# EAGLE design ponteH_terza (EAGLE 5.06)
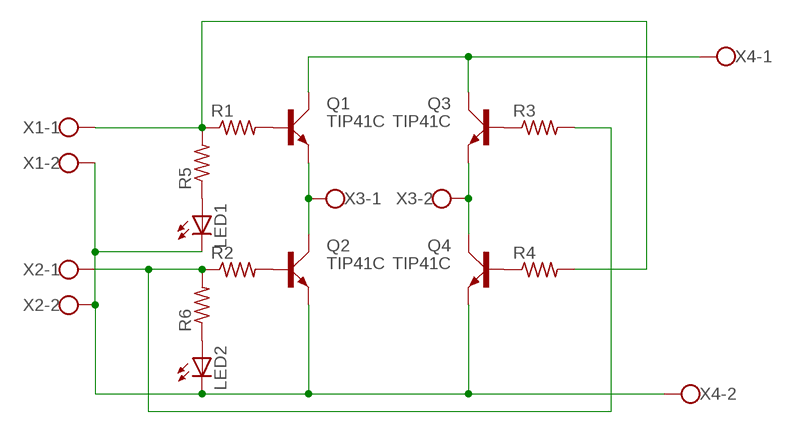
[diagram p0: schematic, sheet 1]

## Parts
LED1  LED3MM  [LED3MM]
LED2  LED3MM  [LED3MM]
Q1  TIP41C  [TO220AV]
Q2  TIP41C  [TO220AV]
Q3  TIP41C  [TO220AV]
Q4  TIP41C  [TO220AV]
R1  R-US_0207/10  [0207/10]
R2  R-US_0207/10  [0207/10]
R3  R-US_0207/10  [0207/10]
R4  R-US_0207/10  [0207/10]
R5  R-US_0207/10  [0207/10]
R6  R-US_0207/10  [0207/10]
X1  W237-02P  [W237-132]
X2  W237-02P  [W237-132]
X3  W237-02P  [W237-132]
X4  W237-02P  [W237-132]

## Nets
N$1: Q1.B R1.2
N$2: Q2.B R2.2
N$3: Q3.B R3.1
N$4: Q4.B R4.1
N$5: R1.1 R4.2 R5.2 X1.1
N$6: R2.1 R3.2 R6.2 X2.1
N$7: LED1.A R5.1
N$8: LED2.A R6.1
N$9: Q1.C Q3.C X4.1
N$10: Q3.E Q4.C X3.2
N$11: Q1.E Q2.C X3.1
N$12: LED1.K(C) LED2.K(C) Q2.E Q4.E X1.2 X2.2 X4.2

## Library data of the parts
LED1 LED2 = led:LED: LED
Q1-Q4 = transistor-power:TIP41C: NPN TRANSISTOR
R1-R6 = resistor:R-US_: RESISTOR, American symbol
X1-X4 = con-wago-508:W237-02P: WAGO SREW CLAMP

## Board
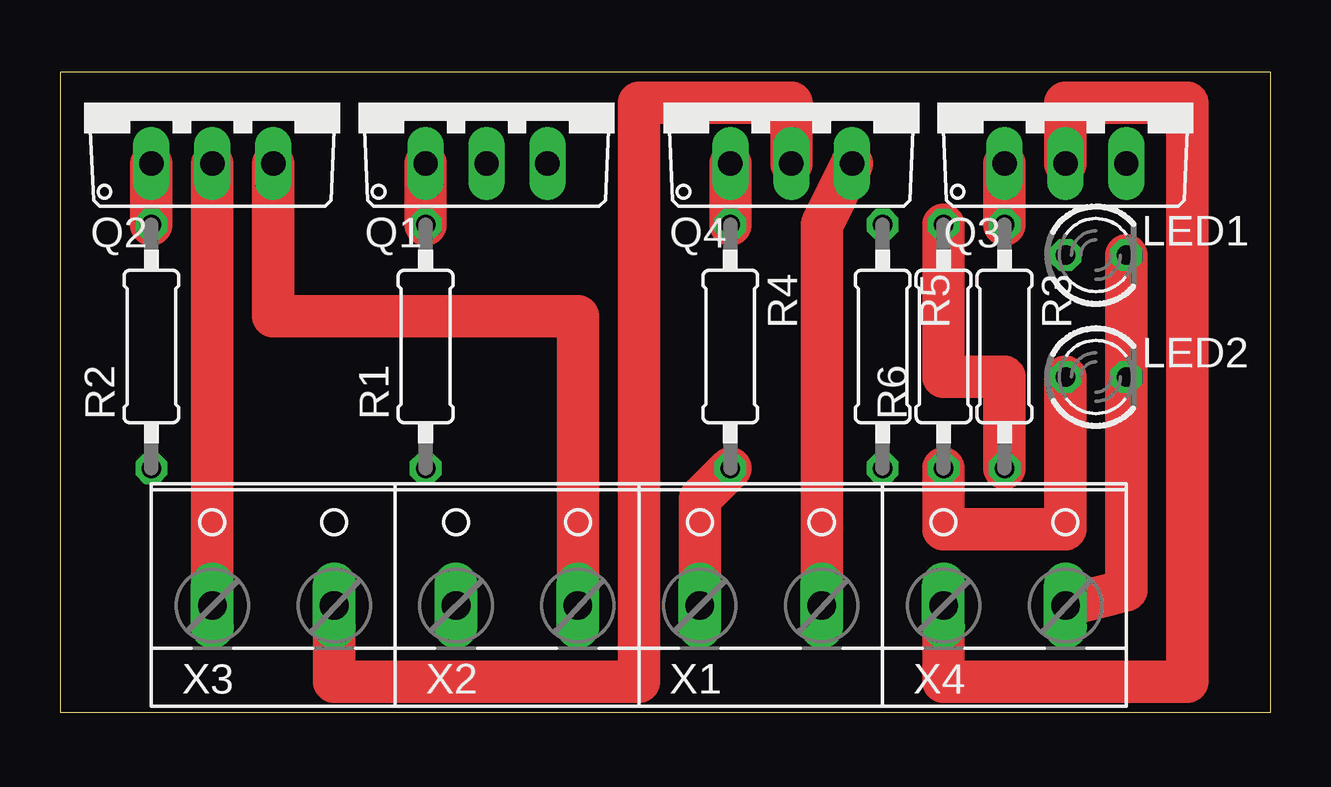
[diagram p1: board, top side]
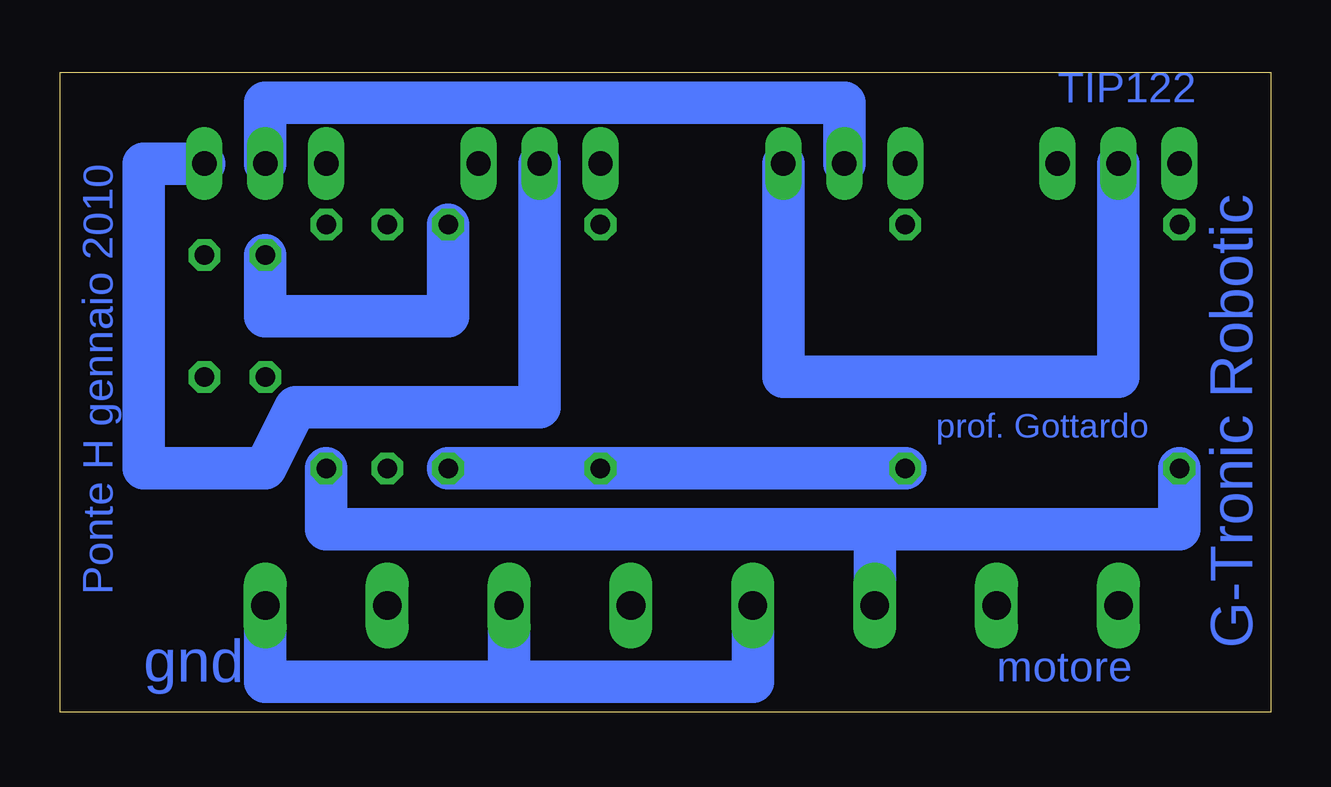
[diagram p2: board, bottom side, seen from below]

Size 50.47 x 26.66 mm. Coordinates in mm from the lower left corner, seen from the top.
Outline: 0,0 50.47,0 50.47,26.66 0,26.66 0,0
Copper layers (1*16): Top 0.035mm / dielectric 1.5mm / Bottom 0.035mm
Design rules "default": minimum track width 10mil, minimum drill 24mil, track to track 8mil, track to pad 8mil, pad to pad 8mil, via to via 8mil, smd to smd 8mil, copper to edge 40mil, drill to drill 8mil, minimum pad ring 10mil, minimum via ring 8mil, stop-mask expansion 4mil, vias tented up to drill 0mil, thermal gap 10mil

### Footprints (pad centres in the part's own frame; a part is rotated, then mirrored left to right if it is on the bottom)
LED3MM = drill 0.813 octagon: A -1.27,0; K 1.27,0
TO220AV = drill 1.016 long: B -2.54,-2.54; C 0,-2.54; E 2.54,-2.54
0207/10 = drill 0.813 octagon: 1 -5.08,0; 2 5.08,0
W237-132 = drill 1.194 long: 1 -2.54,-0.635; 2 2.54,-0.635

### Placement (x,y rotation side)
LED1  43.18,19.05 0 top
LED2  43.18,13.97 0 top
Q1  17.78,25.4 0 top
Q2  6.35,25.4 0 top
Q3  41.91,25.4 0 top
Q4  30.48,25.4 0 top
R1  15.24,15.24 90 top
R2  3.81,15.24 90 top
R3  39.37,15.24 270 top
R4  27.94,15.24 270 top
R5  34.29,15.24 270 top
R6  36.83,15.24 90 top
X1  29.21,5.08 0 top
X2  19.05,5.08 0 top
X3  8.89,5.08 0 top
X4  39.37,5.08 0 top

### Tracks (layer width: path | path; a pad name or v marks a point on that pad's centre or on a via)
N$1
  Top 1.778: R1.2 Q1.B
N$2
  Top 1.778: R2.2 Q2.B
N$3
  Top 1.778: R3.1 Q3.B
N$4
  Top 1.778: R4.1 Q4.B
N$5
  Top 1.778: R4.2 26.67,8.89 X1.1
  Bottom 1.778: R1.1 R4.2 R5.2
N$6
  Top 1.778: R3.2 39.37,13.97 36.83,13.97 R6.2
  Bottom 1.778: R2.1 3.81,7.62 16.51,7.62 | 16.51,7.62 X2.1 | R3.2 39.37,7.62 16.51,7.62
N$7
  Bottom 1.778: R5.1 34.29,16.51 41.91,16.51 LED1.A
N$8
  Top 1.778: R6.1 36.83,7.62 41.91,7.62 LED2.A
N$9
  Top 0.254: X4.1 36.83,2.54
  Top 1.778: X4.1 36.83,1.27 46.99,1.27 46.99,25.4 41.91,25.4 Q3.C
  Bottom 1.778: Q1.C 17.78,25.4 41.91,25.4 Q3.C
N$10
  Top 1.778: Q4.C 30.48,25.4 24.13,25.4 24.13,1.27 11.43,1.27 X3.2
  Bottom 1.778: Q4.C 30.48,12.7 40.64,12.7 41.91,10.16 46.99,10.16 46.99,22.86 Q3.E
N$11
  Top 1.778: X3.1 Q2.C
  Bottom 1.778: Q1.E 20.32,13.97 6.35,13.97 Q2.C
N$12
  Top 1.778: Q2.E 8.89,16.51 21.59,16.51 X2.2 | X4.2 44.45,5.08 LED2.K LED1.K | Q4.E 31.75,20.32 X1.2
  Bottom 1.778: 31.75,1.27 41.91,1.27 X4.2 | 31.75,1.27 X1.2 | 31.75,1.27 21.59,1.27 X2.2

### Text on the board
Bottom: TIP122 | Ponte H gennaio 2010 | G-Tronic Robotic | prof. Gottardo | motore | gnd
